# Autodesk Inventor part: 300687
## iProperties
Created: 2007-11
Part Number: 300687
Document SubType Name: Modeling
Designer: MM
Density: 7.85 g/cm^3
Mass: 235.532 g
Surface Area: 616.109 cm^2
Volume: 30.0041 cm^3
Material: Steel
Description: BACK TOP PLATE
Component Category: Back Component
Author: MM
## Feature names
1. Extrusion1
2. Extrusion2
3. Mirror1
4. Fillet1
5. Extrusion3
6. Fillet2
7. Shell1
8. Extrusion4
9. Sweep2
10. Mirror3
11. Extrusion7
12. Extrusion8
13. Fillet3
14. Extrusion9
15. Fillet4
16. Fillet5
17. Fillet6
18. Extrusion10
19. Fillet7
20. Extrusion11
21. Hole1
